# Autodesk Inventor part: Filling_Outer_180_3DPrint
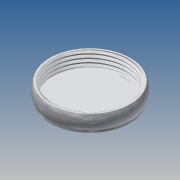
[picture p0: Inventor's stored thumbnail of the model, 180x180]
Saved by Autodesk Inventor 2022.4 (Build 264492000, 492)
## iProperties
Created: 2022-03
Part Number: Filling_Outer_180_3DPrint
Material: Aluminum 6061
Document SubType Name: Modeling
Designer: dotwibo2
Density: 2.71 g/cm^3
Appearance: Aluminum - Flat
Author: dotwibo2
Created: 2021-11
Part Number: outer_filling
Material: PLA filament White
Density: 1.384 g/cm^3
Appearance: White PLA
Mass: 293.665 g
Surface Area: 908.839 cm^2
Volume: 212.186 cm^3
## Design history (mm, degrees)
sketch "Sketch2"
  geometry: L1 (-7, 0)-(42, 0) reference; L2 (0, -17.532)-(0, 105.193) reference; L3 (3, 0)-(3, 80.375); L4 (0, 0)-(0, 83); L5 (0, 83)-(4.8, 83); L6 (4.8, 83)-(5.204, 83.7); L7 (3, 80.375)-(35, 80.375); L8 (35, 80.375)-(35, 83.7); L9 (25.185, 87.661)-(10.612, 87.661); A1 r 30 centre (20.102, 57.661) between (35, 83.7) and (5.204, 83.7); 2 further points
  constraints: 14 end point, 3 horizontal, 3 vertical, 2 point on circle, 2 point on line, 1 centre point, 1 collinear, 1 horizontal alignment, 1 tangent
  dimensions: "d2" = 3 distance between parallel lines of L3 L2; "d3" = 35 distance between parallel lines of L2 L8; "d5" = 160.75 diameter of L7 L1; "d6" = 166 diameter of L5 L1; "d7" = 175.32115 diameter of L9 L1 (derived); "d8" = 30 radius of A1; "d60" = 4.8 distance from line of L5.end L2; "d61" = 60 deg angle of L5 L6; "d62" = 0.7 vertical distance of L5.end L6.end
revolve "Revolution1" sketch "Sketch2" stored, may be unused: angle "d9" = 90 deg
fillet "Fillet1" dims "d54" = 2
sketch "Sketch4"
  geometry: L1 (-2, 82.039)-(-5.501, 75.975); L2 (-6, 75.111)-(-6.499, 75.975); L3 (-10, 82.039)-(-14, 75.111); L4 (-32.712, 0)-(77.606, 0) reference; L5 (0, -109.207)-(0, 129.465) reference; L6 (-14, 75.111)-(-16.952, 80.224); L7 (38.002, 75.111)-(19.603, 75.111); L8 (-10, 82.039)-(-2, 82.039); L9 (61.846, -75.111)-(15.468, -75.111); L10 (-5.501, 75.975)-(-6.499, 75.975); L11 (-6, 73.711)-(-10, 80.639); L12 (-10, 80.639)-(-14, 73.711); L13 (-14, 73.711)-(-6, 73.711); L14 (-9.501, 79.775)-(-10.499, 79.775); L15 (-6, 74.411)-(-10, 81.339); L16 (-10, 81.339)-(-14, 74.411); L17 (-6, 74.411)-(5.616, 94.53); L18 (-6, 73.711)-(6.504, 95.369); L19 (-14, 74.411)-(-6.583, 61.564); L20 (-14, 73.711)-(-15.034, 75.502); L21 (41.021, 77.875)-(-13.906, 77.875); L22 (51.98, 75.375)-(-15.759, 75.375); L23 (-5.501, 75.975)-(-6, 75.111); L24 (-6.499, 75.975)-(-10, 82.039); L25 (-0.83, 80.375)-(-12.491, 80.375); 2 further points
  constraints: 46 end point, 16 parallel, 9 horizontal, 5 point on line, 1 midpoint, 1 vertical alignment, 5 other
  dimensions: "d10" = 30 deg angle of L5 L1; "d11" = 30 deg angle of L5 L2; "d13" = 150.2218 diameter of L2.start L4 (derived); "d14" = 8 distance of L2.start L3.end; "d15" = 0.99778 distance of L1.end L2.end (derived); "d23" = 151.95 diameter of L10 L4 (derived); "d24" = 0.99778 distance of L14.start L14.end (derived); "d25" = 159.55 diameter of L14 L4 (derived); "d27" = 0.7 distance between parallel lines of L11 L2; "d29" = 155.75 diameter of L21 L4; "d55" = 6 distance from line of L5 L2.start; "d56" = 150.75 diameter of L22 L4; "d57" = 0.6 distance between parallel lines of L22 L10; "d58" = 160.75 diameter of L25 L4 (= d5); "d59" = 0.6 distance between parallel lines of L14 L25 (= d57)
coil "Coil1" sketch "Sketch4" pitch "d30" = 8; turns "d32" = 1; dims "d31" = 50, "d33" = 0, angle "d34" = 90 deg, angle "d35" = 90 deg, "d36" = 0, "d37" = 0
sketch "Sketch5"
  geometry: L1 (13.877, 65)-(26.123, 65); L2 (26.123, 65)-(35, 80.375); L3 (35, 80.375)-(5, 80.375); L4 (5, 80.375)-(13.877, 65); L5 (-7, 0)-(42, 0) reference; L6 (0, -16.075)-(0, 96.45) reference; 1 further point
  constraints: 8 end point, 1 horizontal, 1 parallel
  dimensions: "d40" = 160.75 diameter of L3 L5 (= d5); "d45" = 130 diameter of L1 L5; "d46" = 35 distance from line of L6 L2.end; "d47" = 5 distance from line of L6 L3.end; "d48" = 60 deg angle of L3 L2; "d49" = 60 deg angle of L3 L4 (= d48)
revolve "Revolution2" sketch "Sketch5" stored, may be unused: angle "d41" = 90 deg
combine "Combine1"
  body "Solid4"
sketch "Sketch6"
  geometry: L1 (-11.942, 75.085)-(13.932, 75.085); L2 (13.932, 75.085)-(13.932, 69.276); L3 (13.932, 69.276)-(-11.942, 69.276); L4 (-11.942, 69.276)-(-11.942, 75.085); 1 further point
  constraints: 2 other
emboss "Emboss1" sketch "Sketch6" dims "d2" = 3, "d3" = 35, "d5" = 160.75, "d6" = 166, "d7" = 175.32115 (derived), "d8" = 30, "d23" = 151.95 (derived), "d60" = 4.8, "d61" = 60 deg, "d62" = 0.7, "d63" = 0.2, "d64" = 0
node "NEW_FILLING"
body "Solid1"
